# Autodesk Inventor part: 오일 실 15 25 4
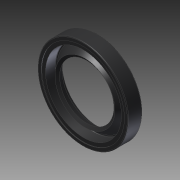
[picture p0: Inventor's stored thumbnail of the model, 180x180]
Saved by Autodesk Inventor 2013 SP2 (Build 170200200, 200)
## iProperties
Created: 2024-11
Part Number: 오일 실 15 25 4
Material: Generic
Document SubType Name: Modeling
Designer: a
Density: 1 g/cm^3
Author: a
변환 표준: STEP AP214IS
전처리기: Build: 200, Release: 2013 SP2 Update 6 - Date: Thu 07/17/2014
전송 단위: 밀리미터
불확실성: 0.01
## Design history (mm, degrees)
node "오일 실 15 25 41"
body "Solid1"
node "기준1"
